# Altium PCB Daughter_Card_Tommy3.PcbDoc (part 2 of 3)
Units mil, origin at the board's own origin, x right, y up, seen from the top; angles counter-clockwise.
Board outline 2032.68 x 3237.01 mil, 8 copper layers (Top Layer, GND, AUX Routing (LVDS), 2.5V, AUX Route Vert, AUX Route Horz, GND (Plane2), Bottom Layer), stack 61.2 mil thick; 218 components, 194 nets, 1097 pads, 500 vias.
Unrouted connection lines stored in the file: 161.
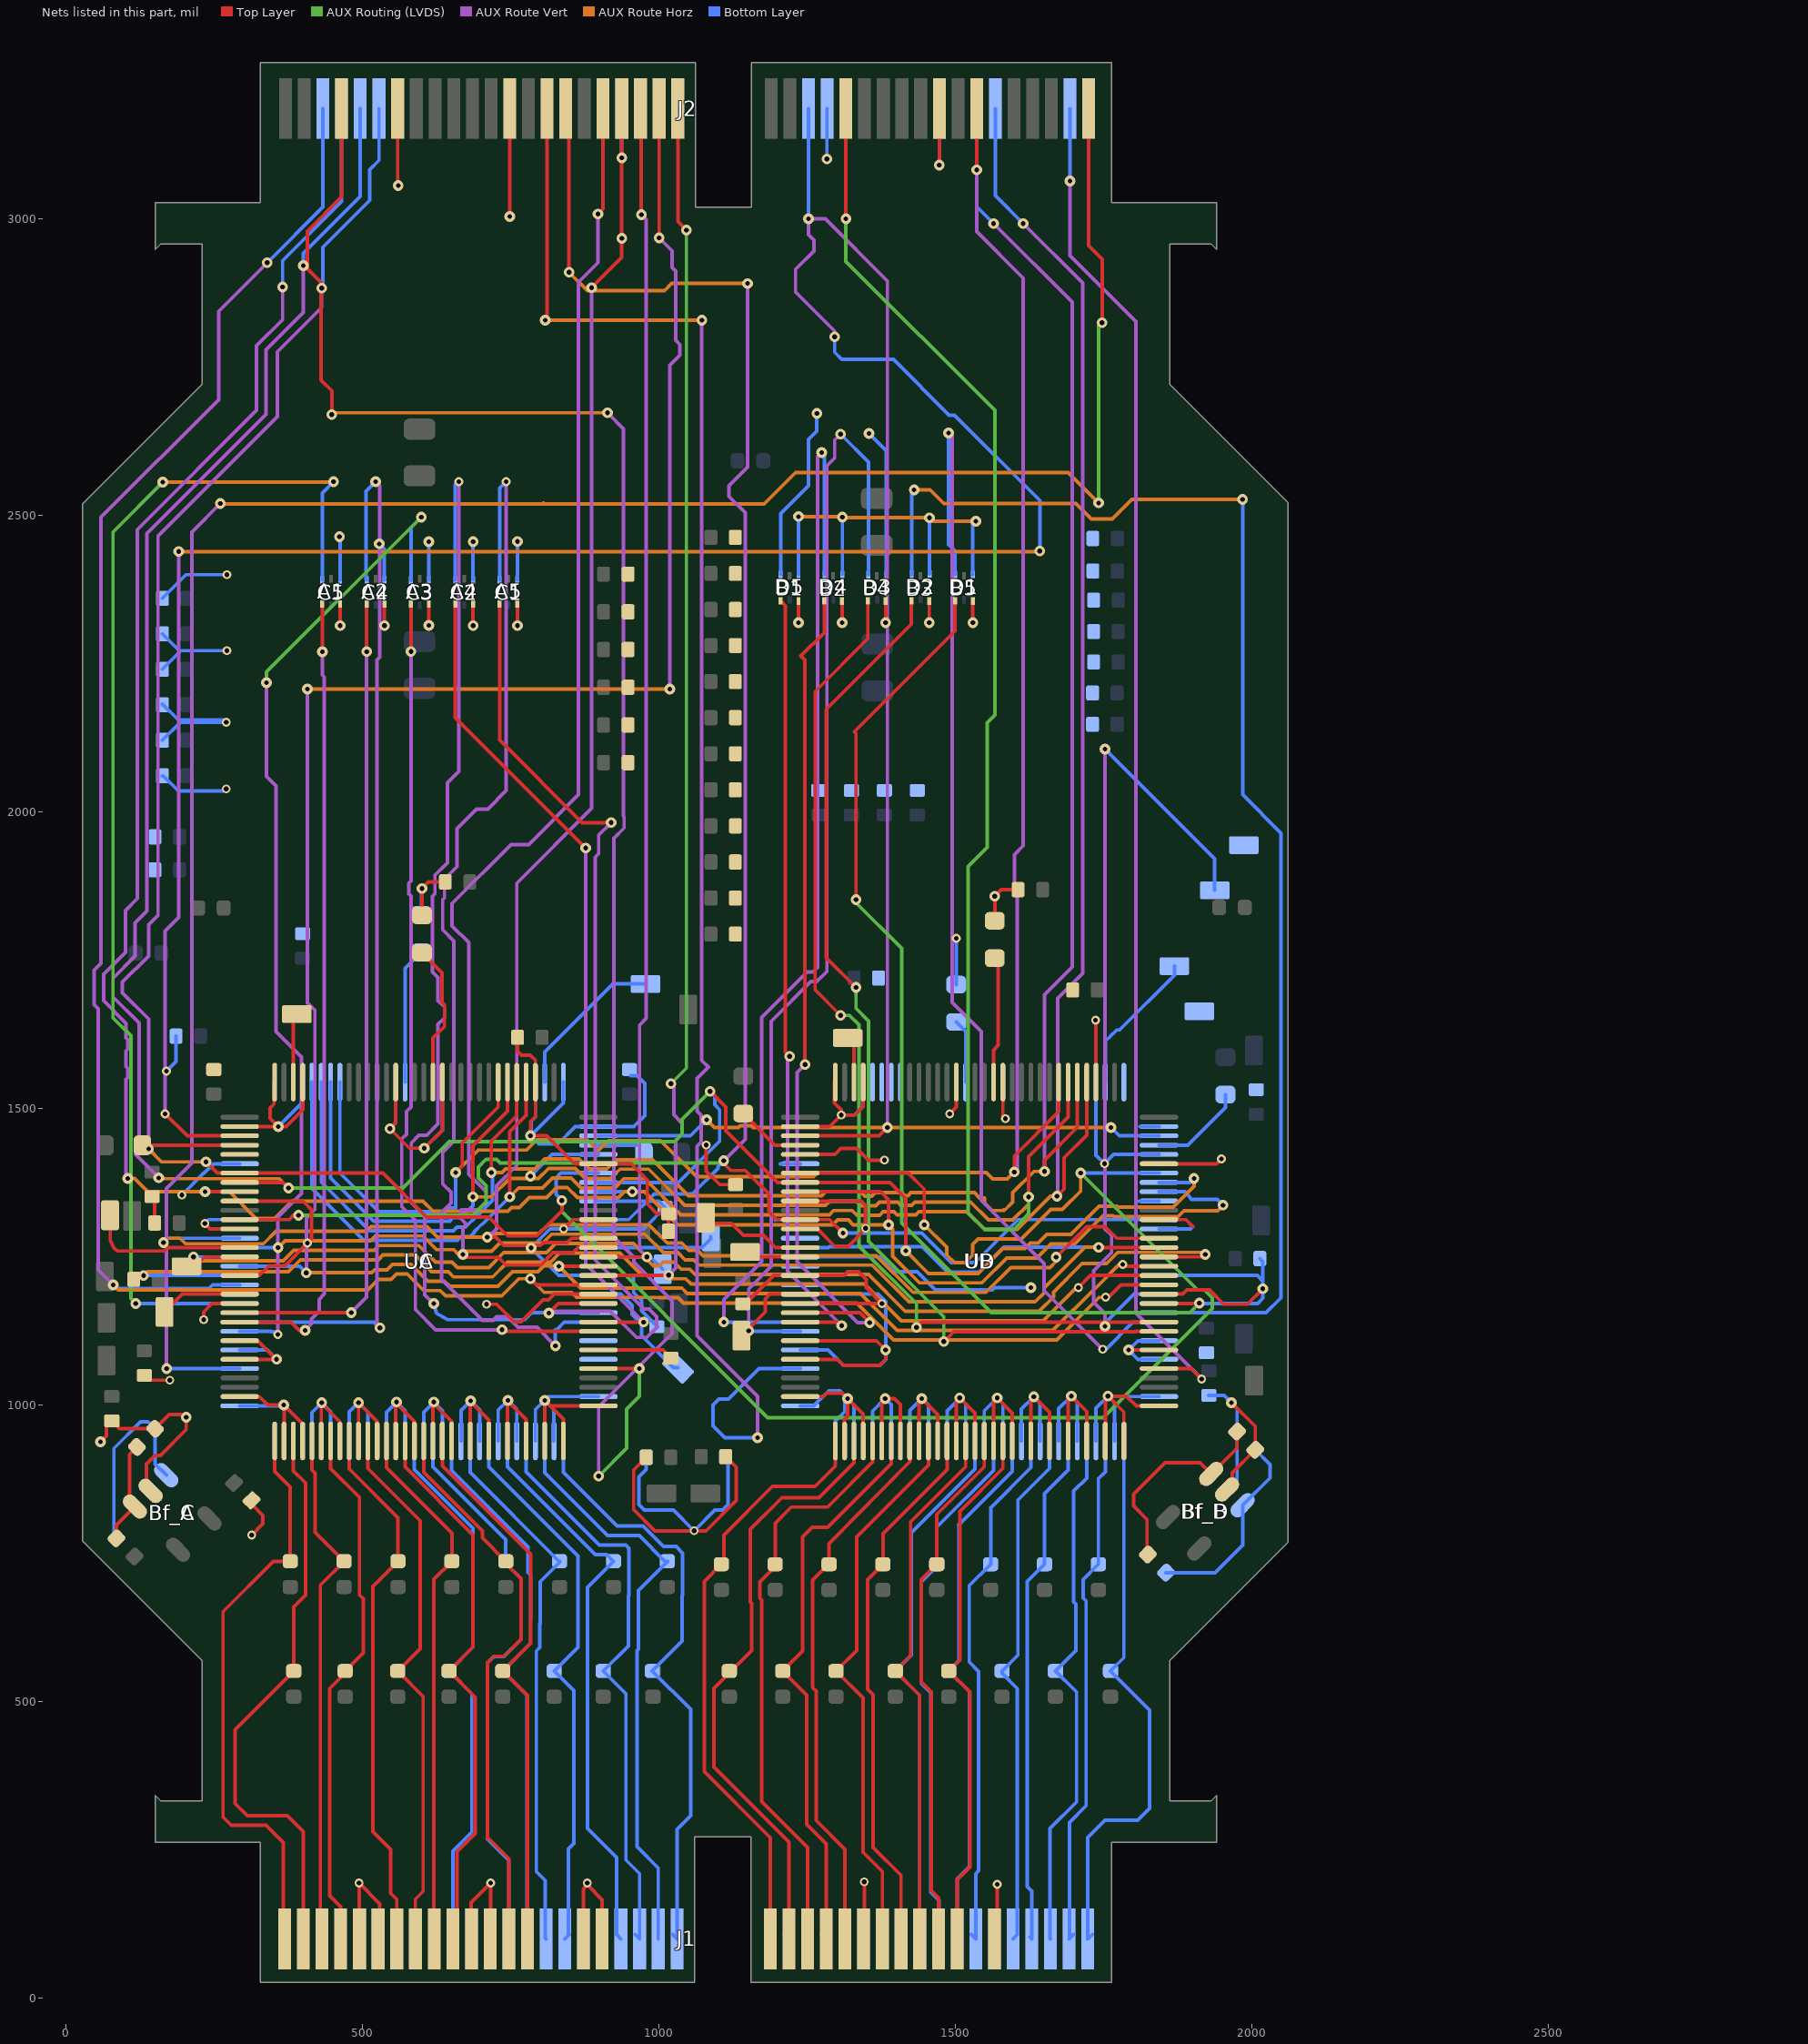
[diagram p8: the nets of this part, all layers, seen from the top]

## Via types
v1: diameter 18, hole 8, Top Layer to Bottom Layer, 106 vias
v2: diameter 18, hole 8, Top Layer to AUX Route Horz, 56 vias
v3: diameter 15, hole 8, Top Layer to Bottom Layer, 53 vias
v4: diameter 18, hole 8, AUX Route Vert to Bottom Layer, 42 vias
v5: diameter 18, hole 8, AUX Route Horz to Bottom Layer, 40 vias
v6: diameter 18, hole 8, Top Layer to AUX Route Vert, 34 vias
v7: diameter 18, hole 8, Top Layer to GND, 33 vias
v8: diameter 18, hole 8, GND (Plane2) to Bottom Layer, 27 vias
v9: diameter 18, hole 8, AUX Routing (LVDS) to Bottom Layer, 23 vias
v10: diameter 18, hole 8, Top Layer to AUX Routing (LVDS), 22 vias
v11: diameter 15, hole 8, Top Layer to 2.5V, 13 vias
v12: diameter 18, hole 8, Top Layer to 2.5V, 13 vias
v13: diameter 15, hole 8, Top Layer to GND, 10 vias
v14: diameter 18, hole 8, 2.5V to Bottom Layer, 8 vias
v15: diameter 15, hole 8, GND (Plane2) to Bottom Layer, 4 vias
v16: diameter 15, hole 8, Top Layer to AUX Route Horz, 4 vias
v17: diameter 18, hole 8, AUX Route Vert to AUX Route Horz, 4 vias
v18: diameter 15, hole 8, 2.5V to Bottom Layer, 2 vias
v19: diameter 18, hole 8, AUX Routing (LVDS) to AUX Route Vert, 2 vias
v20: diameter 15 (per signal layer), hole 8, Top Layer to GND, 1 vias
v21: diameter 15, hole 8, AUX Routing (LVDS) to Bottom Layer, 1 vias
v22: diameter 15, hole 8, Top Layer to AUX Route Vert, 1 vias
v23: diameter 8, hole 8, Top Layer to AUX Route Horz, 1 vias

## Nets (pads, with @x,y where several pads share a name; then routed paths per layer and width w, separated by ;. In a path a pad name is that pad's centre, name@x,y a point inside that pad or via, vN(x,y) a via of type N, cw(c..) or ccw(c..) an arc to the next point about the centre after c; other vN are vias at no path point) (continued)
DO_13: J2.68 UA.72 UB.72 UC.72 UD.72 | length 3654.4
  Top Layer w6: v1(657,1392) 668,1403 668,1442 728.57,1502.57 UA.72@728.57,1544.47 ; v6(1535.46,3082.46) J2.68@1535.46,3186 ; v2(1599,1393) 1599,1420 1673.88,1494.88 UB.72@1673.88,1544.47
  AUX Route Vert w6: v6(1535.46,3082.46) 1535.46,2978.54 1614,2900 1614,1943 1599,1928 1599,1872.74 1604,1867.74 1604,1398 v2(1599,1393)
  AUX Route Horz w6: v1(657,1392) 695,1430 776.75,1430 793.75,1447 878.25,1447 895.25,1430 898.49,1430 914.21,1445.72 1002.28,1445.72 1063,1385 1260.75,1385 1267.75,1392 1551.63,1392 1562.63,1381 1587,1381 v2(1599,1393)
  Bottom Layer w6: UC.72@461.67,1544.47 461.67,1391.33 527,1326 640.01,1326 646.01,1332 657,1332 v1(657,1392)
  other v17: 1599,1393
DO_14: J2.54 UA.71 UB.71 UC.71 UD.71 | length 4078.8
  Top Layer w6: v1(686,1351) 686,1437 744.27,1495.27 UA.71@744.27,1544.47 ; v6(1314.98,3000.02) J2.54@1314.98,3186 ; v2(1623,1351) 1623,1419 1689.58,1485.58 UB.71@1689.58,1544.47
  AUX Routing (LVDS) w6: v6(1314.98,3000.02) 1314.98,2928.02 1566,2677 1566,2163.74 1553,2150.74 1553,1940.11 1521,1908.11 1521,1324 1549,1296 1599.11,1296 1623,1323 v2(1623,1351)
  AUX Route Horz w6: v1(686,1351) 716.89,1351 747.89,1382 796.63,1382 813.63,1399 858.37,1399 875.37,1382 918.37,1382 934.09,1397.72 982.4,1397.72 1043.12,1337 1280.63,1337 1287.63,1344 1332.37,1344 1340.37,1336 1365.26,1336 1371.26,1342 1402.74,1342 1407.74,1337 1426.26,1337 1431.26,1342 1525.26,1342 1555.26,1312 1596.37,1312 1623,1338.63 v2(1623,1351)
  Bottom Layer w6: UC.71@445.97,1544.47 445.97,1383.03 519,1310 646.63,1310 652.63,1316 666,1316 686,1336 v1(686,1351)
DO_15: J2.67 UA.70 UB.70 UC.70 UD.70 | length 3830
  Top Layer w6: v1(717,1392) 717,1445 759.97,1487.97 UA.70@759.97,1544.47 ; v2(1650,1394) 1650,1413 1705.28,1468.28 UB.70@1705.28,1544.47
  AUX Route Vert w6: v4(1564,2992) 1696.45,2859.55 1696.45,1786.33 1696.45,1738.33 1650,1691.89 v2(1650,1394)
  AUX Route Horz w6: v1(717,1392) 735.26,1392 741.26,1398 790.01,1398 807.01,1415 864.99,1415 881.99,1398 911.75,1398 927.46,1413.72 989.03,1413.72 1049.75,1353 1274.01,1353 1281.01,1360 1338.99,1360 1346.99,1352 1358.63,1352 1364.63,1358 1409.37,1358 1414.37,1353 1419.63,1353 1424.63,1358 1531.89,1358 1540.51,1349.37 1549,1349.37 1549,1340.89 1561.89,1328 1580.11,1328 1581.06,1328.94 1582,1328 1596,1342 1596,1358 1632,1394 v2(1650,1394)
  Bottom Layer w6: UC.70@430.27,1544.47 430.27,1375.73 512,1294 653.26,1294 659.26,1300 673.26,1300 694.26,1321 695,1321 719,1345 719,1390 v1(717,1392) ; 1535.46,3020.54 J2.67@1535.46,3186 ; 1536,3020 v4(1564,2992)
  other v6: 1650,1394
DO_16: J2.69 UA.69 UB.69 UC.69 UD.69 | length 3933.8
  Top Layer w6: v1(748,1351) 748,1461 775.67,1488.67 UA.69@775.67,1544.47 ; v2(1671,1352) 1683,1364 1683,1417 1720.98,1454.98 UB.69@1720.98,1544.47
  AUX Route Vert w6: v4(1614,2992) 1714,2892 1714,1728 1672,1686 1672,1353 v2(1671,1352)
  AUX Route Horz w6: v1(748,1351) 763,1366 803.26,1366 820.26,1383 851.74,1383 868.74,1366 925,1366 940.72,1381.72 975.77,1381.72 1036.49,1321 1287.26,1321 1294.26,1328 1325.74,1328 1333.74,1320 1371.89,1320 1377.89,1326 1396.11,1326 1401.11,1321 1432.89,1321 1437.89,1326 1518.63,1326 1548.63,1296 1604,1296 1660,1352 v2(1671,1352)
  Bottom Layer w6: UC.69@414.57,1544.47 414.57,1365.43 502,1278 659.89,1278 665.89,1284 681,1284 688,1291 688,1292.11 700.89,1305 702,1305 v1(748,1351) ; J2.69@1566.95,3186 1566.95,3039.05 v4(1614,2992)
  other v6: 1671,1352
GND: A1.2 A2.2 A3.2 A4.2 A5.2 B1.2 B2.2 B3.2 B4.2 B5.2 Bf_A.2 Bf_B.2 Bf_C.2 Bf_D.2 C1.2 C1A.1 C1B.1 C1D.1 C2.2 C2A.1 C2B.1 C2C.1 C2D.1 C3.2 C3A.1 C3B.1 C3D.1 C4.2 C4A.1 C4B.1 C4C.1 C4D.1 C5.2 C5A.1 C5B.1 C5D.1 C6A.1 C6B.1 C6C.1 C6D.1 C7A.1 C7B.1 C7D.1 C8A.1 C8B.1 C8D.1 C9A.1 C9B.1 C9C.1 C9D.1 C10A.1 C10B.1 C10C.1 C10D.1 C11A.1 C11B.1 C11C.1 C11D.1 C12A.1 C12B.1 C12C.1 C12D.1 C13A.1 C13B.1 C13C.1 C13D.1 C14A.1 C14B.1 C14C.1 C14D.1 CDisA.1 CDisB.1 CDisC.1 CDisD.1 CN_A.1 CN_B.1 CN_C.1 CN_D.1 CP_A.1 CP_B.1 CP_C.1 CP_D.1 Cr_A.1 Cr_B.1 Cramp_C.1 Cramp_D.1 D1.2 D2.2 D3.2 D4.2 D5.2 J1.9 J1.10 J1.11 J1.12 J1.21 J1.22 J1.23 J1.24 J1.33 J1.34 J1.35 J1.36 J1.55 J1.56 J1.69 J1.70 J2.14 J2.26 J2.37 J2.51 J2.63 J2.64 R1_A.1 R1_B.1 R1_C.1 R1_D.1 R_BF2_A.1 R_BF2_B.1 R_BF2_C.1 R_BF2_D.1 UA.2 UA.4 UA.6 UA.8 UA.10 UA.12 UA.14 UA.16 UA.18 UA.20 UA.22 UA.24 UA.26 UA.28 UA.30 UA.32 UA.33 UA.39 UA.45 UA.53 UA.59 UA.68 UA.78 UA.83 UA.93 UA.96 UA.98 UA.101 UA.106 UA.109 UA.114 UA.117 UA.121 UA.123 UA.127 UB.2 UB.4 UB.6 UB.8 UB.10 UB.12 UB.14 UB.16 UB.18 UB.20 UB.22 UB.24 UB.26 UB.28 UB.30 UB.32 UB.33 UB.39 UB.45 UB.53 UB.59 UB.68 UB.78 UB.83 UB.93 UB.96 UB.98 UB.101 UB.106 UB.109 UB.114 UB.117 UB.121 UB.123 UB.127 UC.2 UC.4 UC.6 UC.8 UC.10 UC.12 UC.14 UC.16 UC.18 UC.20 UC.22 UC.24 UC.26 UC.28 UC.30 UC.32 UC.33 UC.39 UC.45 UC.53 UC.59 UC.68 UC.78 UC.83 UC.93 UC.96 UC.98 UC.101 UC.106 UC.109 UC.114 UC.117 UC.121 UC.123 UC.127 UD.2 UD.4 UD.6 UD.8 UD.10 UD.12 UD.14 UD.16 UD.18 UD.20 UD.22 UD.24 UD.26 UD.28 UD.30 UD.32 UD.33 UD.39 UD.45 UD.53 UD.59 UD.68 UD.78 UD.83 UD.93 UD.96 UD.98 UD.101 UD.106 UD.109 UD.114 UD.117 UD.121 UD.123 UD.127 | length 18789.9
  Top Layer w6: v7(58,938) 68,948 CP_A.1@68,972.33 ; CP_A.1@77,973.33 90.33,960 R_BF2_A.1@150,960 ; CN_A.1@132,1050 140,1042 v20(175,1042) ; Bf_A.2@142.4,855.33 135.4,862.33 135.4,900.69 149.94,915.22 159.22,915.22 202.53,958.53 v7@202.53,977.47 ; C4A.1@145,1351.33 149.33,1347 CDisA.1@149.33,1307 ; R_BF2_A.1@147,957 R_BF2_A.1@150,960 ; v7(202.53,979.53) v7@202.53,977.47 ; v3(232,1144) 232,1157 246.02,1171.02 246.32,1171.02 ; v3(234,1306) 242.78,1297.22 ; 243.08,1296.92 UA.109@292.62,1296.92 ; 246.32,1171.32 UA.117@292.62,1171.32 ; UA.127@292.62,1014.32 325.68,1014.32 340,1000 v7(367,1000) v7@367.47,999.53 ; UA.123@292.62,1077.12 v1(354.88,1077.12) 323.48,1108.52 UA.121@292.62,1108.52 ; UA.114@292.62,1218.42 325.42,1218.42 342,1235 369,1235 v13(407,1273) 414,1280 414,1329.11 401.11,1342 ; UA.106@292.62,1344.02 398.98,1344.02 ; UA.98@292.62,1469.62 v1(357.62,1469.62) ; C11A.1@312.62,839.38 312.62,833.38 332,814 332,800 v3(313,781) ; UA.96@350.47,1544.47 350.47,1507.47 344,1501 344,1483.24 v1(357.62,1469.62) ; UA.2@367.47,939.47 v7@367.47,999.53 ; UA.4@398.87,939.47 398.87,968.13 v7@367.47,999.53 ; UA.93@398.87,1544.47 398.87,1497.87 370.62,1469.62 v1(357.62,1469.62) ; UA.6@430.27,939.47 430.27,1003.27 461.67,971.87 UA.8@461.67,939.47 ; v7(462,2314) A1.2@462,2350.5 ; UA.10@493.07,939.47 493.07,1003.93 524.47,972.53 UA.12@524.47,939.47 ; J1.9@494.57,100 494,100.57 v3(494,194) 529,159 J1.11@529,102.94 ; v7(536.75,2314.25) A2.2@536.75,2350.5 ; UA.14@555.87,939.47 v7@555.87,1003.87 ; UA.83@555.87,1544.47 555.87,1475.87 v1(546,1466) 579,1433 v1(604,1433) 634.37,1463.37 UA.78@634.37,1544.47 ; v8(557,1005) v7@555.87,1003.87 ; J2.14@559.08,3186 559.08,3055.08 v7(560,3056) ; UA.16@587.27,939.47 587.27,972.47 v7@555.87,1003.87 ; R1_A.1@600,1825.5 v1(600,1871) 611,1882 C12A.1@639.33,1882 ; v7(611.5,2314.5) A3.2@611.5,2350.5 ; UA.18@618.67,939.47 618.67,1003.67 650.07,972.27 UA.20@650.07,939.47 ; UA.22@681.47,939.47 681.47,1006.47 712.87,975.07 UA.24@712.87,939.47 ; J1.21@683,100.54 683,161 v3(716,194) J1.23@716,100.96 ; v7(686.25,2314.25) A4.2@686.25,2350.5 ; v13(709,1170) 726,1170 755.78,1140.22 767.22,1140.22 804,1177 813,1177 823.02,1187.02 UA.45@897.62,1187.02 ; UA.26@744.27,939.47 744.27,1007.27 775.67,975.87 UA.28@775.67,939.47 ; v7(748,3004) 748.06,3004.06 J2.26@748.06,3186 ; v7(761,2314) A5.2@761,2350.5 ; C13A.1@761.33,1620 761.33,1596.67 768.03,1589.97 782.71,1589.97 791.37,1581.31 UA.68@791.37,1544.47 791.37,1486.37 783,1478 v8(783,1454) 810,1454 856.88,1407.12 860,1407.12 ; UA.30@807.07,939.47 807.07,1007.93 816.38,998.62 ; UA.32@838.47,939.47 838.47,976.53 816.38,998.62 ; v13(839,1297) 854.62,1312.62 UA.53@897.62,1312.62 ; 860.3,1406.82 UA.59@897.62,1406.82 953.18,1406.82 980,1380 980,1339 996.67,1322.33 C3A.1@1016,1322.33 1015.67,1322 C2A.1@1015.67,1293 ; J1.33@872.52,100 872.52,184.52 v3@879,191 ; v3(879,194) v3@879,191 ; UA.33@897.62,998.62 816.38,998.62 ; UA.39@897.62,1092.82 1006.51,1092.82 C1A.1@1020,1079.33 C1A.1@1020,1083.42 ; J1.35@904.02,100 904.02,165.98 v3@879,191 ; CN_B.1@978.33,912 957,890.67 957,824 993,788 v3(1059,788) 1079,788 1130,839 1130,895 1130.34,895 CP_B.1@1112.34,913 ; v13(1079.37,1438.37) 1079.37,1394.37 1102.07,1371.67 CDisB.1@1129,1371.67 ; Cr_B.1@1141,1170.66 1145.29,1170.66 1192.75,1218.12 ; 1192.75,1218.42 UB.114@1237.93,1218.42 1277.58,1218.42 ; v7(1235,2319) B1.2@1235,2355.5 ; UB.127@1237.93,1014.32 1277.32,1014.32 1283,1020 1309,1020 v7(1318,1011) ; UB.123@1237.93,1077.12 1300.88,1077.12 1311,1067 1371.76,1067 1381.88,1077.12 v7@1381.88,1092.88 ; UB.121@1237.93,1108.52 1366.48,1108.52 v7(1382,1093) ; UB.117@1237.93,1171.32 v13(1375.68,1171.32) 1349,1198 1349,1212.11 1336.11,1225 1317.89,1225 1311.61,1218.72 1277.58,1218.72 ; UB.109@1237.93,1296.92 1267.08,1296.92 1296,1268 1319.11,1268 1348,1296.89 v13(1348,1298) 1348,1337 1341.28,1343.72 ; UB.106@1237.93,1344.02 1340.98,1344.02 ; UB.101@1237.93,1422.52 1282.52,1422.52 ; UB.98@1237.93,1469.62 1287.62,1469.62 v3(1307,1489) ; 1282.52,1422.82 1296.82,1422.82 1306.5,1432.5 1333.5,1432.5 1353,1413 v3(1380,1413) ; UB.96@1295.78,1544.47 1295.78,1508.93 1307,1497.7 v3(1307,1489) ; v7@1308.5,2317.5 v7(1308.5,2319) B2.2@1308.5,2355.5 ; UB.2@1312.78,939.47 1312.78,975.78 1318,981 v7(1318,1011) ; UB.4@1344.18,939.47 1344.18,984.82 v7(1318,1011) ; UB.93@1344.18,1544.47 1344.18,1503.18 1330,1489 v3(1307,1489) ; J1.55@1344.96,100 1346,101.04 v3(1346,196) ; UB.6@1375.58,939.47 1375.58,1005.58 v7(1381,1011) 1397,1011 1406.98,1001.02 UB.8@1406.98,939.47 ; v7(1382,2319) B4.2@1382,2355.5 ; UB.10@1438.38,939.47 v7@1438.38,1006.38 ; v7(1443,1011) 1469.78,984.22 UB.12@1469.78,939.47 ; v7(1455.5,2319) B3.2@1455.5,2355.5 ; v1(1472.46,3090.54) J2.64@1472.46,3186 ; v13(1490,1491) 1501.18,1502.18 UB.83@1501.18,1544.47 ; UB.14@1501.18,939.47 1501.18,1006.18 v7(1507,1012) 1532.58,986.42 UB.16@1532.58,939.47 ; v7(1529,2319) B5.2@1529,2355.5 ; R1_B.1@1555.98,1813.48 1555.98,1820.11 1565.35,1829.48 1566,1829.48 v1(1566,1858) 1577,1869 C12B.1@1605.33,1869 ; UB.18@1563.98,939.47 1563.98,1005.98 v7(1570,1012) 1595.38,986.62 UB.20@1595.38,939.47 ; J1.69@1565.43,100 1562,103.43 1570,111.43 v3(1570,192) ; UB.78@1579.68,1544.47 1579.68,1487.32 v13(1584,1483) ; UB.22@1626.78,939.47 1626.78,1008.78 v7(1632,1014) 1658.18,987.82 UB.24@1658.18,939.47 ; UB.26@1689.58,939.47 1689.58,1009.58 v7(1695,1015) 1720.98,989.02 UB.28@1720.98,939.47 ; v13(1736,1649) 1736.68,1648.32 UB.68@1736.68,1544.47 ; UB.30@1752.38,939.47 v7@1752.38,1010.38 ; UB.32@1783.78,939.47 1783.78,988.22 v7(1757,1015) 1788.15,1015 1804.53,998.62 UB.33@1842.93,998.62 ; v1(1791.82,1092.82) UB.39@1842.93,1092.82 ; UB.45@1842.93,1187.02 1883.02,1187.02 1890,1194 1928,1194 1952,1170 1992,1170 v1(2018,1196) ; UB.53@1842.93,1312.62 1888.38,1312.62 1900,1301 ; UB.59@1842.93,1406.82 1939.82,1406.82 v13(1948,1415) ; Bf_B.2@1957.6,857.6 1966.6,857.6 1966.6,885.98 R_BF2_B.1@2005.31,924.69 2005.31,964 1965.31,1004 v7(1965,1004) ; R_BF2_A.1@150,960 174,984 196,984 v7@202.53,977.47 ; 398.98,1344.02 399.09,1344.02 401.11,1342 ; 398.98,1344.02 401,1342 401.11,1342
  AUX Route Horz w6: v5(1235,2498) 1308,2498 v5(1309,2497) 1310,2496 v1(1456,2496) 1462,2490 v1(1534,2490)
  Bottom Layer w6: C3D.1@162.45,2061 163.68,2061 189.48,2035.2 266.2,2035.2 v3(270,2039) ; C14D.1@162.45,2120.84 192.6,2151 v3(270,2151) 266.11,2154.89 189.48,2154.89 162.45,2181.92 C13D.1@162.45,2180.68 ; C12D.1@162.45,2240.53 193.92,2272 ; C11D.1@162.45,2300.37 190.82,2272 193.92,2272 ; C10D.1@162.45,2360.21 202.24,2400 v3(271,2400) ; v15(169,1563) 185.33,1579.33 C4C.1@185.33,1622 ; v15(195,1354) 232,1391 233,1391 248.82,1406.82 UC.59@292.62,1406.82 ; v3(234,1306) 240.62,1312.62 UC.53@292.62,1312.62 ; v3(271,2272) 193.92,2272 ; UC.33@292.62,998.62 365.62,998.62 v7(367,1000) ; UC.39@292.62,1092.82 339.18,1092.82 v1(354.88,1077.12) ; v1(357.62,1469.62) 398.87,1510.87 UC.68@398.87,1544.47 ; UC.28@414.57,939.47 414.57,987.57 v8(431,1004) 445.97,989.03 UC.26@445.97,939.47 ; v8(461,2464) 462,2463 C5.2@462,2391.5 ; UC.24@477.37,939.47 477.37,988.37 v8(493,1004) 508.77,988.23 UC.22@508.77,939.47 ; v8(528,2452) 536.75,2443.25 C4.2@536.75,2391.5 C4.2@537,2391.75 ; UC.20@540.17,939.47 540.17,988.17 v8(557,1005) 571.57,990.43 UC.18@571.57,939.47 ; v1(546,1466) 555.87,1475.87 UC.78@555.87,1544.47 ; R1_C.1@599,1826.5 599,1870 v1(600,1871) ; UC.16@602.97,939.47 602.97,987.97 v8(620,1005) 634.37,990.63 UC.14@634.37,939.47 ; v1(604,1433) 634.37,1463.37 UC.83@634.37,1544.47 ; C3.2@611.5,2391 v8(611.5,2455.5) ; UC.12@665.77,939.47 665.77,990.77 v8(682,1007) 697.17,991.83 UC.10@697.17,939.47 ; C2.2@686.25,2391.32 v8(686.25,2455.75) ; UC.8@728.57,939.47 728.57,991.57 v8(745,1008) 759.97,993.03 UC.6@759.97,939.47 ; C1.2@761,2391.32 v8(761,2456) ; v8(783,1386) 819.52,1422.52 UC.101@897.62,1422.52 ; UC.4@791.37,939.47 791.37,992.37 v8(807,1008) ; UC.93@791.37,1544.47 791.37,1485.63 784,1478.26 v8@784,1455 ; UC.2@822.77,939.47 822.77,992.23 v8(807,1008) ; UC.96@838.47,1544.47 838.47,1509.47 v8@784,1455 ; UC.127@897.62,1014.32 813.32,1014.32 v8(807,1008) ; UC.106@897.62,1344.02 999.32,1344.02 CDisC.1@1010,1333.34 974.66,1298 ; v9(937,3103) J2.37@937.03,3186 ; 945.58,1217.52 953.86,1217.52 957,1214.37 957,1189.71 970.2,1176.51 970.2,1159.03 997.23,1132 Cramp_C.1@996,1132 ; 945.58,1218.42 UC.114@897.62,1218.42 830.58,1218.42 v8(784,1265) 815.92,1296.92 UC.109@897.62,1296.92 973.58,1296.92 ; C1D.1@952,1555.34 962.66,1555.34 975.8,1542.2 975.8,1488.17 957.54,1469.92 ; 957.24,1469.62 UC.98@897.62,1469.62 858.62,1469.62 829,1440 797,1440 v8(783,1454) v8@784,1455 ; CP_C.1@978.33,912 978.33,891.33 966,879 966,832.37 975.37,823 1024,823 v3(1059,788) 1094,823 1106.63,823 1116,832.37 1116,913 CN_C.1@1112,913 ; 1196,1312 1196.62,1312.62 UD.53@1237.93,1312.62 ; 1203.96,1406.82 UD.59@1237.93,1406.82 UD.59@1237.98,1406.87 ; D5.2@1235,2400.5 v5(1235,2498) ; UD.33@1237.93,998.62 1260.62,998.62 1286,1024 1305,1024 v7(1318,1011) ; UD.39@1237.93,1092.82 1285.18,1092.82 1311,1067 1372,1067 1382,1077 v7(1382,1093) 1382,1174 1368.98,1187.02 UD.45@1237.93,1187.02 ; v8(1283,3101) 1283,3185.51 J2.51@1283.49,3186 ; UD.32@1297.08,939.47 1297.08,973.08 1313,989 1313,1006 v7(1318,1011) ; v3(1307,1489) 1329,1489 1344.18,1504.18 UD.68@1344.18,1544.47 ; D4.2@1309,2400.5 v5(1309,2497) ; UD.30@1328.48,939.47 1328.48,1000.52 v7(1318,1011) ; v5(1354,2638) 1383,2609 D3.2@1383,2400.5 ; UD.28@1359.88,939.47 1359.88,989.88 v7(1381,1011) 1391.28,1000.72 UD.26@1391.28,939.47 ; UD.24@1422.68,939.47 1422.68,990.68 v7(1443,1011) 1454.08,999.92 UD.22@1454.08,939.47 ; D2.2@1456,2401 v1(1456,2496) ; v1(1472.46,3090.54) J2.63@1472.46,3186 ; UD.20@1485.48,939.47 1485.48,990.48 v7(1507,1012) 1516.88,1002.12 UD.18@1516.88,939.47 ; R1_D.1@1501,1708.99 v15(1501,1787) ; 1501.18,1510.51 UD.78@1501.18,1544.47 ; D1.2@1529,2400.5 1529,2485 v1(1534,2490) ; UD.16@1548.28,939.47 1548.28,990.28 v7(1570,1012) 1579.68,1002.32 UD.14@1579.68,939.47 ; 1579.68,1510.51 UD.83@1579.68,1544.47 ; UD.12@1611.08,939.47 1611.08,993.08 v7(1632,1014) 1642.48,1003.52 UD.10@1642.48,939.47 ; UD.8@1673.88,939.47 1673.88,993.88 v7(1695,1015) 1705.28,1004.72 UD.6@1705.28,939.47 ; UD.4@1736.68,939.47 1736.68,994.68 v7(1757,1015) v8@1757.68,1014.32 ; UD.93@1736.68,1544.47 1736.68,1421.32 v15@1750.88,1407.12 ; v15@1751.12,1407.12 1766.52,1422.52 UD.101@1842.93,1422.52 ; UD.2@1768.08,939.47 1768.08,1003.92 v8@1757.68,1014.32 ; 1808.96,1344.02 UD.106@1842.93,1344.02 ; UD.98@1811.06,1469.62 UD.98@1842.93,1469.62 ; UD.127@1842.93,1014.32 v8@1757.68,1014.32 ; UD.123@1842.93,1077.12 1807.52,1077.12 v1(1791.82,1092.82) 1807.52,1108.52 UD.121@1842.93,1108.52 ; UD.117@1842.93,1171.32 2009.32,1171.32 2018,1180 v1(2018,1196) 2018,1209 ; UD.114@1842.93,1218.42 2008.58,1218.42 2018,1209 ; UD.109@1842.93,1296.92 1895.92,1296.92 1900,1301 ; CP_D.1@1927,1016.33 1952.67,1016.33 v7(1965,1004) 1974.69,994.31 R_BF2_D.1@1974.69,955.31 1974.69,874.69 Bf_D.2@1957.6,857.6 ; Cramp_D.1@2013,1247 2018,1242 2018,1209
  other v7: 431,1004 493,1004 557,1005 620,1005 682,1007 745,1008 807,1008 783,1454
  other v8: 367,1000 1965,1004 1318,1011 1381,1011 1443,1011 1507,1012 1570,1012 1632,1014 1695,1015 1757,1015 1382,1093
  other v15: 1751,1407
ISEL_A: ISELA.1 UA.112 | length 81.2
  Top Layer w6: ISELA.1@218,1234 233.82,1249.82 UA.112@292.62,1249.82
ISEL_B: ISELB.1 UB.112 | length 96.3
  Top Layer w6: ISELB.1@1145,1258 1153.18,1249.82 UB.112@1237.93,1249.82
ISEL_C: ISELC.1 UC.112 | length 116.9
  Bottom Layer w6: UC.112@897.62,1249.82 952.18,1249.82 ; 952.18,1249.52 985.48,1249.52 ISELC.1@1006,1229
ISEL_D: ISELD.1 UD.112
NetA1_1: A1.1 UA.119 | length 1355.5
  Top Layer w6: UA.119@292.62,1139.92 379.08,1139.92 ; 379.38,1139.62 393,1126 v6(403,1126) ; v6(432,2270) A1.1@432,2350.82
  AUX Route Vert w6: v6(403,1126) 414,1137 414,1145 426.75,1157.75 426.75,1178.37 435.5,1187.12 435.5,2227.5 432,2231 v6(432,2270)
NetA2_1: A2.1 UA.118 | length 1393.3
  Top Layer w6: UA.118@292.62,1155.62 v6@480.37,1155.62 ; v6(506.75,2270.25) A2.1@506.75,2350.82
  AUX Route Vert w6: v6(480.75,1156) 506.75,1182 506.75,2210 v6(506.75,2270.25)
NetA3_1: A3.1 UA.41 | length 1528.6
  Top Layer w6: v6(581.5,2270.5) A3.1@581.5,2350.82 ; v6@737.78,1124.22 UA.41@897.62,1124.22
  AUX Route Vert w6: v6(581.5,2270.5) 581.5,1883.61 578,1880.11 578,1861.89 581.5,1858.39 581.5,1502.61 574,1495.11 574,1456.74 566,1448.74 566,1334.63 589,1311.63 589,1161 623,1127 v6(735,1127)
NetA4_1: A4.1 UA.42 | length 1418.8
  Top Layer w6: A4.1@656.25,2350.82 656.25,2158.75 v6(876,1939) ; UA.42@897.62,1139.92 v6(973.92,1139.92)
  AUX Route Vert w6: v6(876,1939) 876,1237.84 v6(973.92,1139.92)
NetA5_1: A5.1 UA.44 | length 1684.8
  Top Layer w6: A5.1@731,2350.82 731,2121 870,1982 v6(919,1982) ; v6(814,1155) 830.32,1171.32 UA.44@897.62,1171.32
  AUX Route Vert w6: v6(814,1155) 817.32,1158.32 917.68,1158.32 962,1114 979.11,1114 995.92,1130.81 995.92,1149.03 983.03,1161.92 974.55,1161.92 892,1244.46 892,1923.89 898,1929.89 898,1961 v6(919,1982)
NetB1_1: B1.1 UB.119 | length 1339.9
  Top Layer w6: B1.1@1205,2355.82 1213,2347.83 1213,1595 v6(1220,1588) ; UB.119@1237.93,1139.92 1302.08,1139.92 v6(1308,1134)
  AUX Route Vert w6: v6(1220,1588) 1216.5,1584.5 1216.5,1225.5 v6(1308,1134)
NetB2_1: B2.1 UB.118 | length 1428.1
  Top Layer w6: UB.118@1237.93,1155.62 1338.38,1155.62 v6(1355,1139) ; v6(1246,1574) 1246,2256 1239,2263 1278.5,2302.5 B2.1@1278.5,2355.82
  AUX Route Vert w6: v6(1246,1574) 1232.5,1560.5 1232.5,1241.5 1335,1139 v6(1355,1139)
NetB3_1: B3.1 UB.41 | length 1759.9
  Top Layer w6: v10(1332,1704) 1282,1754 1282,2173 1425.5,2316.5 B3.1@1425.5,2355.82 ; v10(1480,1107) 1496.92,1123.92 1802.55,1123.92 ; 1802.85,1124.22 UB.41@1842.93,1124.22
  AUX Routing (LVDS) w6: v10(1332,1704) 1332,1668.63 1353,1647.63 1353,1276 1480,1149 v10(1480,1107)
NetB4_1: B4.1 UB.42 | length 1753.9
  Top Layer w6: v10(1306,1657) 1263,1700 1263,2203 1352,2292 B4.1@1352,2355.82 ; v10(1434,1131) 1442.92,1139.92 UB.42@1842.93,1139.92
  AUX Routing (LVDS) w6: v10(1306,1657) 1321,1657 1337,1641 1337,1268 1434,1171 v10(1434,1131)
NetB5_1: B5.1 UB.44 | length 1791.9
  Top Layer w6: v1(1332,1852) 1332,2132 1329,2135 1499,2305 B5.1@1499,2355.82 ; UB.44@1842.93,1171.32 1910.32,1171.32 v10(1911,1172)
  AUX Routing (LVDS) w6: v1(1332,1852) 1332,1847 1409,1770 1409,1307 1560,1156 1895,1156 v10(1911,1172)
NetBf_A_3: Bf_A.3 R_BF1_A.1 R_BF2_A.2 | length 181.2
  Top Layer w6: R_BF1_A.1@84.69,775.31 84.69,797.63 Bf_A.3@115.95,828.89 106.95,828.89 106.95,916.95 R_BF2_A.2@119.38,929.38
NetBf_B_3: Bf_B.3 R_BF1_B.1 R_BF2_B.2 | length 393.9
  Top Layer w6: R_BF1_B.1@1833.12,748.1 R_BF1_B.1@1824.18,748.1 1822.78,749.49 1822.78,807.22 1800,830 1800,850 1853,903 1912.21,903 Bf_B.3@1931.16,884.05 ; Bf_B.3@1915.02,867.92 Bf_B.3@1931.16,884.05 ; R_BF2_B.2@1974.69,955.31 1974.69,927.58 Bf_B.3@1931.16,884.05
NetBf_C_3: Bf_C.3 R_BF1_C.1 R_BF2_C.2 | length 332.5
  Bottom Layer w6: R_BF1_C.1@84.69,775.31 80.51,779.49 80.51,926.99 125.52,972 138,972 R_BF2_C.2@150,960 150,900.62 Bf_C.3@168.84,881.78
NetBf_D_3: Bf_D.3 R_BF1_D.1 R_BF2_D.2 | length 338.4
  Bottom Layer w6: R_BF1_D.1@1854.8,717.47 1937.47,717.47 1984.05,764.05 Bf_D.3@1984.05,831.16 2030,877.11 2030,900 R_BF2_D.2@2005.31,924.69
NetC1_1: C1.1 UC.119 | length 1947.4
  AUX Route Vert w6: v3(742,2557) 742,2036 711,2005 692,2005 659,1972 659,1907.74 638,1886.74 638,1855.26 635,1852.26 635,1801.26 654,1782.26 654,1445 635,1426 635,1373.11 649,1359.11 649,1340.89 633,1324.89 633,1212 702,1143 719.89,1143 725.89,1149 744.11,1149 762.11,1131 794,1131 v4(825,1100)
  Bottom Layer w6: C1.1@731,2391 731,2546 v3(742,2557) ; v4(825,1100) 825,1127 827.17,1127 839.78,1139.62 840.08,1139.62 ; 840.08,1139.92 UC.119@897.62,1139.92
NetC2_1: C2.1 UC.118 | length 1925.3
  AUX Route Vert w6: v4(620,1171) 605,1186 605,1318.26 582,1341.26 582,1442.11 594.89,1455 608.11,1455 627,1473.89 627,1641.89 638,1652.89 638,1671.11 627,1682.11 627,1721.11 618,1730.11 618,1857.89 622,1861.89 622,1893.37 643,1914.37 643,2049.11 662,2068.11 v3(662,2557)
  Bottom Layer w6: v4(620,1171) 624.5,1154.67 643.28,1144 773.38,1144 785,1155.62 UC.118@897.62,1155.62 ; C2.1@656.25,2391 656.25,2551.25 v3(662,2557)
NetC3_1: C3.1 UC.41 | length 1707.1
  AUX Route Vert w6: v1(338,2218) 338,2060.07 354,2044.07 354,1630.01 397,1587.01 397,1356.89 357,1316.89 v3(357,1119)
  AUX Routing (LVDS) w6: v1(338,2218) 338,2236 v9(599,2497)
  Bottom Layer w6: UC.41@292.62,1124.22 345.78,1124.22 ; 345.78,1123.92 352.08,1123.92 v3(357,1119) ; C3.1@581.5,2390.68 581.5,2479.5 v9(599,2497)
NetC4_1: C4.1 UC.42 | length 1847.1
  AUX Route Vert w6: v9(522,2557) 528.75,2550.25 528.75,2261.14 524,2256.39 524,1135 v9(529,1130)
  Bottom Layer w6: UC.42@292.62,1139.92 519.08,1139.92 v9(529,1130) ; C4.1@506.75,2391.18 506,2391.92 506,2541 v9(522,2557)
NetC5_1: C5.1 UC.44 | length 2071.3
  AUX Routing (LVDS) w6: v9(117.32,1171.32) 109,1179.63 109,1623 79,1653 79,2472 v9(163,2556)
  AUX Route Horz w6: v9(163,2556) v9@450,2556
  Bottom Layer w6: v9(117.32,1171.32) UC.44@292.62,1171.32 ; C5.1@432,2391.18 432,2538 v9(451,2557)
NetD1_1: D1.1 UD.119 | length 2010.1
  AUX Route Vert w6: v4(1488,2639) 1494,2633 1494,1679 1543,1630 1543,1344.89 1649,1238.89 1649,1193 v3(1748,1094)
  Bottom Layer w6: v4(1488,2639) 1488,2451 1499,2440 D1.1@1499,2400.18 ; v3(1748,1094) 1753.11,1094 1798.92,1139.81 1798.92,1139.92 UD.119@1842.93,1139.92
NetD2_1: D2.1 UD.118 | length 2321.3
  AUX Route Horz w6: v1(1430,2543) 1457,2543 1480,2520 1703,2520 1729,2494 1764,2494 1797,2527 v5(1984,2527)
  Bottom Layer w6: D2.1@1426,2400.68 1426,2539 v1(1430,2543) ; UD.118@1842.93,1155.62 2023.62,1155.62 2048.8,1180.8 2048.8,1964.2 1984,2029 v5(1984,2527)
NetD3_1: D3.1 UD.41 | length 1924.5
  AUX Route Vert w6: v4(1151,1125) 1151,1196 1189,1234 1189,1647 1256,1714 1266,1714 1283,1731 1283,2583.89 1296,2596.89 1296,2627 v4(1306,2637)
  Bottom Layer w6: v4@1151.78,1124.22 UD.41@1237.93,1124.22 ; v4(1306,2637) 1353,2590 D3.1@1353,2400.18
NetD4_1: D4.1 UD.42 | length 1877
  AUX Route Vert w6: v4(1109.08,1139.92) 1109.08,1178.08 1173,1242 1173,1653.63 1249.37,1730 1259.37,1730 1267,1737.63 1267,2599 v1(1274,2606)
  Bottom Layer w6: v4(1109.08,1139.92) UD.42@1237.93,1139.92 ; v1(1274,2606) 1279,2601 D4.1@1279,2400.18
NetD5_1: D5.1 UD.44 | length 297.1
  Bottom Layer w6: D5.1@1205,2400.18 1205,2503 1252,2550 1252,2628 1266,2642 v1(1266,2672)
NetDONEA_1: DONEA.1 UA.94 | length 116.9
  Top Layer w6: UA.94@383.17,1544.47 383.17,1653.17 DONEA.1@389,1659
NetDONEB_1: DONEB.1 UB.94 | length 78.9
  Top Layer w6: DONEB.1@1318,1619 1328.48,1608.52 UB.94@1328.48,1544.47
NetDONEC_1: DONEC.1 UC.94 | length 268.1
  Bottom Layer w6: UC.94@807.07,1544.47 807.07,1595.07 922,1710 DONEC.1@977,1710
NetDONED_1: DONED.1 UD.94 | length 246.9
  Bottom Layer w6: UD.94@1752.38,1544.47 1752.38,1614 1762.13,1623 1771.57,1632.43 1776.43,1632.43 1869,1725 DONED.1@1869,1740
NetMON_TimEB_1: MON_TimEB.1 UB.116 | length 140.8
  Top Layer w6: MON_TimEB.1@1139,1117 1179,1157 1179,1179 1187.02,1187.02 UB.116@1237.93,1187.02
NetMON_TimingA_1: MON_TimingA.1 UA.116 | length 139.1
  Top Layer w6: MON_TimingA.1@166,1157 196.02,1187.02 UA.116@292.62,1187.02
NetMON_TimingC_1: MON_TimingC.1 UC.116 | length 206.1
  Bottom Layer w6: UC.116@897.62,1187.02 934.98,1187.02 954.2,1167.8 954.2,1152.4 970.2,1136.4 970.2,1117.06 1024.26,1063 MON_TimingC.1@1032,1063
NetMON_TimingD_1: MON_TimingD.1 UD.116 | length 1429.1
  AUX Route Vert w6: v4(1752,1133) 1752,1154.01 1732.5,1173.51 1732.5,1226.39 1763,1256.89 1763,1286.11 1752,1297.11 v4(1752,2106)
  Bottom Layer w6: v4(1752,1133) 1752,1138.02 1801,1187.02 UD.116@1842.93,1187.02 ; v4(1752,2106) 1937,1921 MON_TimingD.1@1937,1868
NetR1_A_2: R1_A.2 UA.79 | length 241.9
  Top Layer w6: R1_A.2@600,1762.5 633.77,1728.74 633.77,1679 638,1674.77 638,1638.03 618.67,1619 UA.79@618.67,1544.47
NetR1_B_2: R1_B.2 UB.79 | length 214.8
  Top Layer w6: UB.79@1563.98,1544.47 1563.98,1598.47 1571.98,1606.47 1571.98,1747.53 R1_B.2@1566,1753.5
NetR1_C_2: R1_C.2 UC.79 | length 230.4
  Bottom Layer w6: UC.79@571.57,1544.47 571.57,1736.07 R1_C.2@599,1763.5
NetR1_D_2: R1_D.2 UD.79 | length 107.7
  Bottom Layer w6: R1_D.2@1501,1646 1516.58,1630.42 ; UD.79@1516.88,1544.47 1516.88,1630.12
NetR2_A_2: R2_A.2 UA.100 | length 163.9
  Top Layer w6: R2_A.2@128.71,1438.22 UA.100@292.62,1438.22
NetR2_B_2: R2_B.2 UB.100 | length 118
  Top Layer w6: R2_B.2@1142,1491.5 1195.29,1438.22 UB.100@1237.93,1438.22
NetR2_C_2: R2_C.2 UC.100 | length 63.7
  Bottom Layer w6: UC.100@897.62,1438.22 R2_C.2@961.29,1438.22
NetR2_D_2: R2_D.2 UD.100 | length 160.3
  Bottom Layer w6: UD.100@1842.93,1438.22 1891.71,1438.22 1955,1501.5 R2_D.2@1955,1523.5
PCLK_A: J2.8 UA.37 | length 3205.9
  Top Layer w6: v2(448,2670) 448,2709.89 430,2727.89 430,2892.63 407,2915.63 407,2979 464.59,3036.59 J2.8@464.59,3186 ; UA.37@897.62,1061.42 v10(966.58,1061.42)
  AUX Route Vert w6: v19(898,880) 898,997 1022,1121 1022,1175.89 957.18,1240.71 957.18,1249.19 923.5,1282.87 923.5,1955.39 941,1972.89 941,1992.11 940,1993.11 940,2646 v1(913,2673)
  AUX Routing (LVDS) w6: v19(898,880) 945,927 945,993.11 966.58,1014.69 v10(966.58,1061.42)
  AUX Route Horz w6: v2(448,2670) 451,2673 v1(913,2673)
PCLK_B: J2.77 UB.37 | length 2312.9
  Top Layer w6: UB.37@1842.93,1061.42 1897.58,1061.42 ; 1897.88,1061.12 v22(1915,1044)
  AUX Route Vert w6: v4(1692.87,3063.87) 1692.87,2937.95 1804,2826.82 1804,1155 v22(1915,1044)
  Bottom Layer w6: v4(1692.87,3063.87) J2.77@1692.87,3186
PCLK_C: J2.80 UC.37 | length 3823.5
  Top Layer w6: J2.80@1724.43,3186 1724.43,2954.57 1747,2932 v1(1747,2825)
  AUX Route Vert w6: v4(169.42,1061.42) 169.42,1365.3 212,1407.89 212,2472 v1(260,2520)
  AUX Routing (LVDS) w6: v9(1741,2521) 1741,2819 v1(1747,2825)
  AUX Route Horz w6: v1@261,2521 v1(260,2520) 261,2519 1177.11,2519 1230.11,2572 1690,2572 v9(1741,2521) ; 805,2521 806,2520
  Bottom Layer w6: v4(169.42,1061.42) UC.37@292.62,1061.42
PCLK_D: J2.30 UD.37 | length 2848
  Top Layer w6: v2(808,2829) 808,2824.09 811.05,2824.09 J2.30@811.05,3164.95
  AUX Route Vert w6: v1(1072,2829) 1072,1581 1083,1570 1064,1551 1064,1495.37 1071,1488.37 1071,1443.63 1064,1436.63 1064,1117 1166,1015 v4(1166,945)
  AUX Route Horz w6: v2(808,2829) v1(1072,2829)
  Bottom Layer w6: v4(1166,945) 1110.89,945 1091,964.89 1091,1000 1101,1010 1117,1010 1168.42,1061.42 UD.37@1237.93,1061.42
Ramp: J2.32 UA.108 UB.108 UC.108 UD.108 | length 4140.5
  Top Layer w6: UA.108@292.62,1312.62 376,1312.62 383.38,1320 v10(392,1320) ; J2.32@842.54,3186 848,3180.54 v2(848,2910) ; v1(1109,1412) 1109,1407 1120.5,1395.5 1145.28,1395.5 1185,1355.77 1185,1326 1198.38,1312.62 UB.108@1237.93,1312.62 1287.38,1312.62 v1(1310,1290)
  AUX Route Vert w6: v1(1109,1412) 1145,1448 1145,2504.89 1118,2531.89 1118,2550.11 1149,2581.11 v1(1149,2891)
  AUX Routing (LVDS) w6: v10(392,1320) 686.11,1320 708,1341.89 708,1369.89 695,1382.89 695,1401.11 707.89,1414 726.11,1414 732.11,1408 1105,1408 v1(1109,1412)
  AUX Route Horz w6: v2(848,2910) 879.02,2878.98 1009.14,2878.98 1021.16,2891 v1(1149,2891)
  Bottom Layer w6: UC.108@897.62,1312.62 948.62,1312.62 992,1356 1056,1356 1099,1399 1099,1402 v1(1109,1412) ; v1(1310,1290) 1443,1290 1493,1240 1533,1240 1605.62,1312.62 UD.108@1842.93,1312.62
RampMon_A: RampMONA.1 UA.111 | length 263.8
  Top Layer w6: RampMONA.1@74.48,1311 74.48,1276.89 80.48,1265.52 86.2,1259.8 164.98,1259.8 170.18,1265 171.3,1265 171.82,1265.52 UA.111@292.62,1265.52
RampMon_B: RampMONB.1 UB.111 | length 179.7
  Top Layer w6: RampMONB.1@1079,1316 1088.5,1306.5 1121.5,1306.5 1142,1286 1176,1286 1196.18,1265.82 1196.48,1265.82 ; 1196.48,1265.52 UB.111@1237.93,1265.52
RampMon_C: RampMONC.1 UC.111 | length 199.2
  Bottom Layer w6: UC.111@897.62,1265.52 1072.14,1265.52 1087,1280.37 RampMONC.1@1087,1284
RampMon_D: RampMOND.1 UD.111
RD_CS_S0: J2.5 UA.46 UB.46 UC.46 UD.46 | length 4384.2
  Top Layer w6: v2(783,1213) 793.28,1202.72 UA.46@897.62,1202.72 ; v16(1753,1182) 1753,1181 1755,1179 1778.42,1202.42 ; 1778.72,1202.72 UB.46@1842.93,1202.72
  AUX Route Vert w6: v4(79.28,1202.72) 54,1228 54,1668.01 47,1675.01 47,1732.99 59,1744.99 59,2497 257,2695 257,2844 v4(339,2926)
  AUX Route Horz w6: v4(79.28,1202.72) 88,1194 508.76,1194 526.76,1212 547.89,1212 556.89,1221 575.11,1221 603.11,1193 631.01,1193 640.01,1184 734.62,1184 763.62,1213 v2(783,1213) 806,1190 852.37,1190 860.87,1181.5 999.76,1181.5 1000.26,1181 1031.74,1181 1040.74,1172 1333,1172 1395,1110 1670.62,1110 1742.12,1181.5 v16@1754,1181.5
  Bottom Layer w6: v4(79.28,1202.72) 85.58,1196.42 241,1196.42 247,1202.42 ; 247,1202.72 UC.46@292.62,1202.72 ; v4(339,2926) 433.09,3020.09 J2.5@433.09,3186
RD_CS_S1: J2.44 UA.47 UB.47 UC.47 UD.47 | length 4121.3
  Top Layer w6: UA.47@897.62,1218.42 v2(1016,1219) ; J2.44@1030,3184.48 J2.44@1031.52,3186 1031.52,2995.48 v2(1046,2981) ; v16(1707,1198) 1727.42,1218.42 UB.47@1842.93,1218.42
  AUX Route Vert w6: v2(1016,1219) 1028,1231 1028,1445.89 1039,1456.89 1039,1475.11 1025,1489.11 1025,1537 v19(1020,1542)
  AUX Routing (LVDS) w6: v19(1020,1542) 1046,1568 v2(1046,2981)
  AUX Route Horz w6: v5(130.58,1218.42) 136.88,1224.72 374.72,1224.72 395,1245 526.26,1245 534.26,1253 588.37,1253 616.37,1225 644.26,1225 653.26,1216 719.37,1216 744.37,1241 816.99,1241 832.11,1256.12 933.88,1256.12 971,1219 v2(1016,1219) 1022,1213 1044.99,1213 1053.99,1204 1346.25,1204 1408.25,1142 1647.37,1142 1703.37,1198 v16(1707,1198)
  Bottom Layer w6: v5(130.58,1218.42) UC.47@292.62,1218.42
RD_CS_S2: J2.42 UA.48 UB.48 UC.48 UD.48 | length 4345.9
  Top Layer w6: v2(830.88,1234.12) UA.48@897.62,1234.12 ; v2(1000,2968) J2.42@1000.02,3186 ; v16@1784.88,1234.12 UB.48@1842.93,1234.12
  AUX Route Vert w6: v1(405,1223) 405,1315 419.5,1329.5 419.5,1665.5 407,1678 v1(407,2207) ; v2(1000,2968) 1022,2946 1022,2917.89 1028,2911.89 1028,2795.11 1035,2788.11 1035,2769.89 1018,2752.89 v1(1018,2207)
  AUX Route Horz w6: v1(405,1223) 515.14,1223 520.14,1228 541.26,1228 550.26,1237 581.74,1237 609.74,1209 637.63,1209 646.63,1200 727.99,1200 752.99,1225 795.62,1225 805.62,1235 830,1235 v2(830.88,1234.12) 867.5,1197.5 1006.39,1197.5 1006.89,1197 1038.37,1197 1047.37,1188 1339.63,1188 1401.63,1126 1663.99,1126 1735.49,1197.5 1736.14,1197.5 v16@1775.64,1237 ; v1(407,2207) v1(1018,2207)
  Bottom Layer w6: UC.48@292.62,1234.12 393.88,1234.12 v1(405,1223)
  other v16: 1782,1237
RD_CS_S3: J2.40 UA.49 UB.49 UC.49 UD.49 | length 4452.5
  Top Layer w6: UA.49@897.62,1249.82 v2(979.18,1249.82) ; J2.40@968.53,3186 970,3184.53 v1(970,3007) ; UB.49@1842.93,1249.82 1916.82,1249.82 v2(1921,1254)
  AUX Route Vert w6: v1(970,3007) 978,2999 978,1651.74 967,1640.74 967,1262 v2(979.18,1249.82)
  AUX Route Horz w6: v5(214.82,1249.82) 221.63,1243 366.08,1243 384.08,1261 519.63,1261 527.63,1269 594.99,1269 622.99,1241 650.89,1241 659.89,1232 712.74,1232 737.74,1257 810.37,1257 825.49,1272.12 956.88,1272.12 v2(979.18,1249.82) ; v2@979.18,1246 990.18,1235 1000.89,1235 1006.89,1241 1025.11,1241 1037.11,1229 1051.62,1229 1060.62,1220 1352.88,1220 1414.88,1158 1640.74,1158 1665,1182.26 1665,1190.37 1713.13,1238.5 1754.51,1238.5 1773.51,1257.5 1917.5,1257.5 v2(1921,1254)
  Bottom Layer w6: v5(214.82,1249.82) UC.49@292.62,1249.82 ; UD.49@1237.93,1249.82 1372.18,1249.82 1397.37,1224.63 1435.37,1224.63 1466,1194 1562,1194 1566,1198 v1(1627,1198)
RD_CS_S4: J2.36 UA.50 UB.50 UC.50 UD.50 | length 4578.7
  Top Layer w6: v1(669,1254) 674,1249 729,1249 742,1236 800,1236 821,1257 855,1257 855,1257.52 863,1265.52 UA.50@897.62,1265.52 ; v2(897,3008) 905.54,3016.54 J2.36@905.54,3186 ; v1@1741.48,1265.52 UB.50@1842.93,1265.52
  AUX Route Vert w6: v1(669,1254) 669,1298.89 675,1304.89 665,1314.89 665,1327.63 666.37,1329 695.11,1329 708,1341.89 708,1360.11 695.11,1373 695,1373 679,1389 679,1779.89 651,1807.89 651,1845.63 750.37,1945 780,1945 864,2029 864,2893.11 897,2926.11 v2(897,3008)
  AUX Route Horz w6: v5@359.97,1268 368.97,1277 513.01,1277 521.01,1285 601.62,1285 624.62,1262 653.63,1262 661.63,1254 v1(669,1254) 674.22,1259.22 717.33,1259.22 731.11,1273 803.74,1273 818.86,1288.12 976,1288.12 1007.12,1257 1031.74,1257 1043.74,1245 1058.25,1245 1067.25,1236 1359.51,1236 1421.51,1174 1634.11,1174 1649,1188.89 1649,1197 1718,1266 v1(1741,1266)
  Bottom Layer w6: UC.50@292.62,1265.52 v5(357.48,1265.52) ; UD.50@1237.93,1265.52 1285.52,1265.52 1287,1267 1443.37,1267 1486.37,1224 1539.63,1224 1581.63,1266 v1(1741,1266)
RD_CS_S5: J2.38 UA.51 UB.51 UC.51 UD.51 | length 4148
  Top Layer w6: v1(710,1283) 724,1283 738,1269 799.74,1269 804.74,1274 844.99,1274 852.21,1281.22 UA.51@897.62,1281.22 ; v6(886,2884) 937.03,2935.03 J2.38@937.03,3186 ; v2(1669.5,1249.5) 1721,1301 1752,1301 1771.78,1281.22 UB.51@1842.93,1281.22
  AUX Route Vert w6: v1(710,1283) 712,1283 726,1297 726,1369.89 760,1403.89 760,1880 886,2006 v6(886,2884)
  AUX Route Horz w6: v5(164,1274) 171.22,1281.22 192.22,1281.22 201.44,1272 332.85,1272 353.85,1293 506.38,1293 514.38,1301 608.25,1301 626.25,1283 v1(710,1283) 716,1289 797.11,1289 812.23,1304.12 982.63,1304.12 1013.75,1273 1038.37,1273 1050.37,1261 1064.88,1261 1073.88,1252 1366.14,1252 1428.14,1190 1550.88,1190 1592.88,1232 1659.37,1232 1669.5,1242.13 v2(1669.5,1249.5)
  Bottom Layer w6: v5(164,1274) 171.22,1281.22 UC.51@292.62,1281.22
  other v2: 937,2967
RD_RS_S0: J2.7 UA.105 UB.105 UC.105 UD.105 | length 4534.1
  Top Layer w6: v2(234.28,1359.72) UA.105@292.62,1359.72 ; UB.105@1237.93,1359.72 1373.28,1359.72 ; 1373.58,1359.42 1387,1346 v2(1387,1304)
  AUX Route Vert w6: v4(104,1382) 101,1385 101,1549.01 103.5,1551.51 103.5,1568.49 101,1570.99 101,1597.01 103.5,1599.51 103.5,1616.49 101,1618.99 101,1643.63 63,1681.63 63,1726.37 100,1763.37 100,1834 120,1854 120,2476 321,2677 321,2786 365,2830 v4(365,2885)
  AUX Route Horz w0: 318,1317 353.11,1317
  AUX Route Horz w6: v4(104,1382) 115.37,1382 137.65,1359.72 v2(234.28,1359.72) 275.28,1359.72 318,1317 322,1313 350,1313 381,1344 601.89,1344 618.89,1327 744.89,1327 750.89,1333 764,1333 781,1350 809.89,1350 826.89,1367 845.11,1367 862.11,1350 931.63,1350 941.35,1359.72 v5(954.72,1359.72) 975.14,1359.72 1030.86,1304 1292.89,1304 1300.89,1312 1319.11,1312 1327.11,1304 v2(1387,1304) 1394,1297 1394,1250.89 1438.89,1206 1544.25,1206 1586.25,1248 1636.89,1248 1660.39,1271.5 1700.87,1271.5 1748.37,1319 1765.26,1319 1766.26,1318 1875.04,1318 1884.92,1327.89 1941.89,1327.89 v5(1951,1337) v5@1951,1335
  Bottom Layer w6: v4(365,2885) 365,2929.37 464.59,3028.96 J2.7@464.59,3186 ; UC.105@897.62,1359.72 v5(954.72,1359.72) ; UD.105@1842.93,1359.72 1887.28,1359.72 1897.76,1347 1941,1347 v5(1951,1337)
RD_RS_S1: J2.9 UA.104 UB.104 UC.104 UD.104 | length 4595.6
  Top Layer w6: UA.104@292.62,1375.42 365.58,1375.42 ; 365.58,1375.12 365.88,1375.12 v2(375,1366) ; v1(1086,1529) 1112.27,1502.73 1112.27,1462.73 1199.58,1375.42 UB.104@1237.93,1375.42 1388.58,1375.42 ; 1388.88,1375.12 1416,1348 v2(1416,1260)
  AUX Route Vert w6: v4(156,1383) 156,1383.89 117,1422.89 117,1441.11 123,1447.11 123,1644.26 79,1688.26 79,1719.74 116,1756.74 116,1813 136,1833 136,2469.37 337,2670.37 337,2779.37 400,2842.37 v4(400,2921)
  AUX Routing (LVDS) w6: v2(375,1366) 568.11,1366 646.11,1444 1026.11,1444 1039,1456.89 1039,1482 v1(1086,1529)
  AUX Route Horz w6: v4@156,1381.72 359.28,1381.72 v2(375,1366) ; v2(1416,1260) 1454,1222 1537.63,1222 1579.63,1264 1617.25,1264 1626.25,1273 1639.26,1273 1653.76,1287.5 1694.25,1287.5 1741.75,1335 1771.89,1335 1772.89,1334 1867,1334 1902,1369 v5(1902,1382)
  Bottom Layer w6: v4(400,2921) 400,2941.75 496.09,3037.83 J2.9@496.09,3186 ; UC.104@897.62,1375.42 1032.47,1375.42 1102,1444.95 1102,1498.11 1094,1506.11 1094,1521 v1(1086,1529) ; UD.104@1842.93,1375.42 1895.42,1375.42 v5(1902,1382)
RD_RS_S2: J2.11 UA.103 UB.103 UC.103 UD.103 | length 5327
  Top Layer w6: v2(236,1410) 254.88,1391.12 UA.103@292.62,1391.12 533.88,1391.12 608,1317 712.63,1317 744.63,1285 793.11,1285 836,1327.89 v1(836,1345) ; UB.103@1237.93,1391.12 1419.88,1391.12 1447,1364 v2(1447,1304)
  AUX Route Vert w6: v4(139,1432) 139,1650.89 95,1694.89 95,1713.11 139,1757.11 139,1810 155,1826 155,2465.75 356,2666.75 356,2775.75 431,2850.75 v4(431,2883)
  AUX Routing (LVDS) w6: v1(836,1345) 836,1326 1183,979 1749.11,979 1933,1162.89 1933,1181.11 1920.11,1194 1908,1194 v1(1710.88,1391.12)
  AUX Route Horz w6: v4(139,1432) 161,1410 v2(236,1410) ; v2(1447,1304) 1485,1266 1485,1252.89 1497.89,1240 1516.11,1240 1529,1252.89 1529,1271.11 1537.89,1280 1610.63,1280 1660.63,1330 1680.11,1330 1710.88,1360.77 v1(1710.88,1391.12)
  Bottom Layer w6: v4(431,2883) 433,2885 433,2952.12 512.09,3031.2 512.09,3083.09 527.58,3098.58 J2.11@527.58,3186 ; v1@835,1345 v1(836,1345) 826,1355 826,1383 834.12,1391.12 UC.103@897.62,1391.12 ; v1(1710.88,1391.12) UD.103@1842.93,1391.12
RegCLR: J2.49 UA.99 UB.99 UC.99 UD.99 | length 6258
  Top Layer w6: v16(167,1491) 204.08,1453.92 UA.99@292.62,1453.92 ; UB.99@1237.93,1453.92 1370.92,1453.92 v2(1385,1468)
  AUX Route Vert w6: v16(167,1491) 167,1799 190,1822 v4(190,2439) ; v4(1251.99,3000.01) 1251.99,2973.12 1261,2964.11 1261,2945.89 1230,2914.89 1230,2876.89 1296,2810.89 v4(1296,2801) ; 1261,3000.01 1279.99,3000.01 1385,2895 v2(1385,1468)
  AUX Route Horz w6: v4(190,2439) 1641,2439 v5(1642,2440) ; v5(1080,1481) 1093,1468 1133.89,1468 1136.89,1471 1155.11,1471 1158.11,1468 v2(1385,1468) v5(1762,1468)
  Bottom Layer w6: UC.99@897.62,1453.92 1052.92,1453.92 v5(1080,1481) ; v4(1251.99,3000.01) J2.49@1251.99,3186 ; v4(1296,2801) 1296,2775 1308,2763 1395.11,2763 1489.11,2669 1498,2669 1642,2525 v5(1642,2440) ; v5(1762,1468) 1776.08,1453.92 UD.99@1842.93,1453.92
RFin_1_A: J1.1 R1A.2 UA.1 | length 991.4
  Top Layer w6: UA.1@351.77,939.47 351.77,888.23 377.95,862.05 R1A.2@377.95,736.65 349.63,736.65 264.65,651.68 264.65,305.37 278.37,291.65 337.35,291.65 366.35,262.65 366.35,102.24 J1.1@368.58,100
RFin_1_B: J1.45 R1B.2 UB.1 | length 1019.4
  Top Layer w6: J1.45@1187.48,100 1187.48,270.52 1076,382 1076,702.84 R1B.2@1104.82,731.65 1109,735.84 1109,781 1191,863 1263,863 1297.08,897.08 UB.1@1297.08,939.47
RFin_1_C: J1.44 R1C.2 UC.1 | length 1029.5
  Bottom Layer w6: UC.1@838.47,939.47 838.47,886.47 928.94,796 973,796 1007.54,761.46 1028.68,761.46 1039.76,750.39 1039.76,678.85 1039,678.1 1039,602.31 R1C.2@988.35,551.65 1053,487 1053,308 1030,285 J1.44@1030,100 J1.44@1022.33,107.67
RFin_1_D: J1.80 R1D.2 UD.1 | length 963
  Bottom Layer w6: J1.80@1730.74,107.83 J1.80@1722.91,100 1722.91,270.91 1752,300 1807,300 1827,320 1827,485.88 R1D.2@1761.23,551.65 1783.78,574.2 UD.1@1783.78,939.47 UD.1@1784.16,939.09
RFin_2_A: J1.3 R2A.2 UA.3 | length 984.5
  Top Layer w6: UA.3@383.17,939.47 383.17,889.17 403.75,868.59 403.75,679.61 383.86,659.72 R2A.2@383.86,551.65 285,452.8 285,328 305.35,307.65 372.97,307.65 400.08,280.55 J1.3@400.08,100
RFin_2_B: J1.47 R2B.2 UB.3 | length 1039
  Top Layer w6: J1.47@1211.31,107.67 1218.98,100 1218.98,263.02 1092.55,389.45 1092.55,522.53 1156.02,586 1156.02,665.84 1153.88,667.98 1153.88,790.88 1207,844 1269.85,844 1328.48,902.63 UB.3@1328.48,939.47
RFin_2_C: J1.42 R2C.2 UC.3 | length 995
  Bottom Layer w6: 807.07,885.93 913,780 966.37,780 1009.72,736.65 R2C.2@1013.96,736.65 964.9,687.59 964.9,588.25 962.55,585.91 962.55,255.45 998.5,219.5 J1.42@998.5,100 ; 807.07,886.07 UC.3@807.07,939.47
RFin_2_D: J1.78 R2D.2 UD.3 | length 878.9
  Bottom Layer w6: J1.78@1691.42,100 J1.78@1692,100.58 ; J1.78@1699.09,107.67 J1.78@1692,100.58 ; UD.3@1752.38,939.47 1752.38,887.62 1740.83,876.07 R2D.2@1740.83,731.65 1715.03,705.86 1715.03,674.61 1720,669.64 1720,324.37 1692,296.37 J1.78@1692,100.58
RFin_3_A: J1.5 R3A.2 UA.5 | length 879.8
  Top Layer w6: UA.5@414.57,939.47 414.57,890.43 419.75,885.25 419.75,785.72 R3A.2@468.81,736.65 428.68,696.52 428.68,102.9 J1.5@431.57,100
RFin_3_B: J1.49 R3B.2 UB.5 | length 998.1
  Top Layer w6: J1.49@1242.8,107.67 J1.49@1250.47,100 1250.47,254.16 1173,331.63 1173,671.49 1169.88,674.61 1169.88,702.08 1195.68,727.88 R3B.2@1195.68,731.65 1195.68,800.68 1223,828 1283.88,828 1359.88,904 UB.5@1359.88,939.47
RFin_3_C: J1.40 R3C.2 UC.5 | length 991.6
  Bottom Layer w6: UC.5@775.67,939.47 775.67,887.33 899,764 943.72,764 948.9,758.82 948.9,678.71 948,677.82 948,593.98 R3C.2@905.67,551.65 944,513.32 944,233 967.01,209.99 J1.40@967.01,100 J1.40@959.34,107.67
RFin_3_D: J1.76 R3D.2 UD.5 | length 898.3
  Bottom Layer w6: J1.76@1659.92,100 1659,100.92 1659,286 1704,331 1704,516 R3D.2@1668.35,551.65 1703,586.31 1703,664.01 1699.03,667.98 1699.03,855.03 1720.98,876.98 UD.5@1720.98,939.47
RFin_4_A: J1.7 R4A.2 UA.7 | length 898.6
  Top Layer w6: UA.7@445.97,939.47 445.97,893.03 494.61,844.39 494.61,679.61 501,673.22 501,582.18 R4A.2@470.47,551.65 463.07,544.25 466.85,544.25 444.68,522.08 444.68,173 463.07,154.61 J1.7@463.07,100
RFin_4_B: J1.51 R4B.2 UB.7 | length 971.8
  Top Layer w6: J1.51@1274.3,107.67 J1.51@1281.97,100 1281.97,260.03 1249,293 1249,511 R4B.2@1208.35,551.65 1242,585.31 1242,778 1258,794 1284,794 1391.28,901.28 UB.7@1391.28,939.47
RFin_4_C: J1.38 R4C.2 UC.7 | length 966.6
  Bottom Layer w6: UC.7@744.27,939.47 744.27,896.11 892.37,748 911.76,748 R4C.2@923.1,736.65 879,692.55 879,286 928,237 928,107.51 J1.38@935.51,100
RFin_4_D: J1.74 R4D.2 UD.7 | length 875.7
  Bottom Layer w6: J1.74@1625.03,103.39 J1.74@1628.43,100 1628.43,180.57 1621,188 1621,702.69 R4D.2@1649.97,731.65 1649.97,850.81 1689.58,890.42 UD.7@1689.58,939.47
RFin_5_A: J1.13 R5A.2 UA.9 | length 908
  Top Layer w6: UA.9@477.37,939.47 477.37,892.37 559.67,810.07 R5A.2@559.67,736.65 517,694 517,280.74 547,250.74 547,177 557.56,166.44 J1.13@557.56,100
RFin_5_B: J1.53 R5B.2 UB.9 | length 940.6
  Top Layer w6: J1.53@1305.79,107.67 J1.53@1313.46,100 1313.46,251.16 1265,299.63 1265,517.63 1259,523.63 1259,705 1285.65,731.65 R5B.2@1286.53,731.65 1286.53,766.49 1422.68,904.68 UB.9@1422.68,939.47
RFin_5_C: J1.32 R5C.2 UC.9 | length 940.5
  Bottom Layer w6: UC.9@712.87,939.47 712.87,895.56 863,745.43 863,591.66 R5C.2@822.99,551.65 856,518.65 856,261 847,252 J1.32@847,105.98 ; J1.32@841.02,100 J1.32@847,105.98 ; J1.32@848.69,107.67 J1.32@847,105.98
RFin_5_D: J1.72 R5D.2 UD.9 | length 885.6
  Bottom Layer w6: J1.72@1596.93,100 1604.14,107.21 1604.14,522.08 1578.35,547.88 R5D.2@1578.35,551.65 1605,578.31 1605,840 1658.18,893.18 ; 1658.18,893.82 UD.9@1658.18,939.47
RFin_6_A: J1.15 R6A.2 UA.11 | length 914.7
  Top Layer w6: UA.11@508.77,939.47 508.77,893.23 597,805 597,589.44 R6A.2@559.21,551.65 602,508.87 602,180 589,167 J1.15@589,100.05
RFin_6_B: J1.57 R6B.2 UB.11 | length 947
  Top Layer w6: J1.57@1384,107.54 J1.57@1376.46,100 1376.46,213.54 1344,246 1344,506 R6B.2@1298.35,551.65 1333,586.31 1333,777.85 1454.08,898.92 UB.11@1454.08,939.47
RFin_6_C: J1.30 R6C.2 UC.11 | length 925.5
  Bottom Layer w6: UC.11@681.47,939.47 681.47,886.53 831.35,736.65 R6C.2@832.24,736.65 832.24,735.24 799.18,702.18 799.18,631.36 799,631.18 799,591.65 793,585.65 793,213.39 808,198.39 808,101.53 J1.30@809.53,100
RFin_6_D: J1.68 R6D.2 UD.11 | length 902
  Bottom Layer w6: J1.68@1526.27,107.67 J1.68@1533.94,100 1533.94,209.94 1539,215 1539,550.63 1523,566.63 1523,695.54 R6D.2@1559.11,731.65 1559.11,827.11 1626.78,894.78 UD.11@1626.78,939.47
RFin_7_A: J1.17 R7A.2 UA.13 | length 898
  Top Layer w6: UA.13@540.17,939.47 540.17,894.17 650.53,783.81 R7A.2@650.53,736.65 620.03,706.16 620.03,100.52 J1.17@620.55,100
RFin_7_B: J1.59 R7B.2 UB.13 | length 929.1
  Top Layer w6: J1.59@1400.28,107.67 J1.59@1407.95,100 1407.95,207.05 1361,254 1361,511.63 1351.6,521.03 1351.6,705.86 R7B.2@1377.39,731.65 1377.39,783.39 1485.48,891.48 UB.13@1485.48,939.47
RFin_7_C: J1.28 R7C.2 UC.13 | length 931.2
  Bottom Layer w6: UC.13@650.07,939.47 650.07,890.07 779,761.14 779,717.89 783.18,713.71 783.18,637.99 783,637.81 783,598.28 R7C.2@736.38,551.65 777,511.03 777,101.03 J1.28@778.03,100
RFin_7_D: J1.66 R7D.2 UD.13 | length 910.7
  Bottom Layer w6: 1505,798 1595.38,888.38 ; 1506,797 1506,569.31 R7D.2@1488.35,551.65 1523,517 1523,221.63 1502.44,201.07 J1.66@1502.44,100 J1.66@1508,105.56 ; 1595.38,891.62 UD.13@1595.38,939.47
RFin_8_A: J1.19 R8A.2 UA.15 | length 927.7
  Top Layer w6: UA.15@571.57,939.47 571.57,895.57 686,781.14 686,591.83 R8A.2@645.83,551.65 690,507.48 690,277.74 659,246.74 659,107.67 J1.19@659.72,107.67
RFin_8_B: J1.61 R8B.2 UB.15 | length 916.4
  Top Layer w6: J1.61@1431.78,107.67 J1.61@1439.45,100 1439.45,510.55 R8B.2@1398.35,551.65 1424,577.31 1424,803 1516.88,895.88 UB.15@1516.88,939.47
RFin_8_C: J1.26 R8C.2 UC.15 | length 949.2
  Bottom Layer w6: UC.15@618.67,939.47 618.67,895.67 741.39,772.95 R8C.2@741.39,736.65 741.39,732.88 767.18,707.08 767.18,644.61 767,644.43 767,604.9 738,575.9 721.1,575.9 710.58,565.39 710.58,268.42 746.54,232.46 J1.26@746.54,100
RFin_8_D: J1.64 R8D.2 UD.15 | length 913.3
  Bottom Layer w6: J1.64@1463.28,107.67 J1.64@1470.94,100 1472,101.06 1472,165 1458,179 1458,514.63 1442.46,530.17 1442.46,702.08 1468.25,727.88 R8D.2@1468.25,731.65 1468.25,794.3 1563.98,890.02 UD.15@1563.98,939.47
RFin_9_A: J1.25 R9A.2 UA.17 | length 956.2
  Top Layer w6: UA.17@602.97,939.47 602.97,886.8 702,787.76 702,776.04 R9A.2@741.39,736.65 741.39,732.88 767.18,707.08 767.18,605.08 738.56,576.46 721.66,576.46 710.58,565.39 710.58,270.42 712,269 712.74,269 746.54,235.2 J1.25@746.54,100
RFin_9_B: J1.63 R9B.2 UB.17 | length 906.3
  Top Layer w6: J1.63@1463.28,107.67 J1.63@1470.94,100 1470.94,169.06 1459,181 1459,516 1442,533 1442,705.4 R9B.2@1468.25,731.65 1468.25,815.7 1548.28,895.72 UB.17@1548.28,939.47
RFin_9_C: J1.20 R9C.2 UC.17 | length 926.1
  Bottom Layer w6: UC.17@587.27,939.47 587.27,891 686,792.27 686,591.83 R9C.2@645.83,551.65 684,513.48 684,280 652,248 652,100.05 J1.20@652.05,100
RFin_9_D: J1.62 R9D.2 UD.17 | length 921.8
  Bottom Layer w6: J1.62@1431.78,107.67 J1.62@1439.45,100 1439.45,510.55 R9D.2@1398.35,551.65 1425,578.31 1425,784.75 1532.58,892.32 ; 1532.58,893.42 UD.17@1532.58,939.47
RFin_10_A: J1.27 R10A.2 UA.19 | length 946.1
  Top Layer w0: J1.27@772.14,105.89 J1.27@778.03,100
  Top Layer w6: UA.19@634.37,939.47 634.37,897.63 783.18,748.82 783.18,619 783.18,615.36 783.18,598.46 R10A.2@736.38,551.65 778.03,510 J1.27@778.03,100
RFin_10_B: J1.65 R10B.2 UB.19 | length 908.9
  Top Layer w6: J1.65@1508,105.56 J1.65@1502.44,100 1502.44,199.44 1524,221 1524,516 R10B.2@1488.35,551.65 1507,570.31 1507,820.65 1579.68,893.32 UB.19@1579.68,939.47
